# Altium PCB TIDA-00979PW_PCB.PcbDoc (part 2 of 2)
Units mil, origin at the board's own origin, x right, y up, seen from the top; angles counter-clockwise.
Board outline 2100 x 2800 mil, 4 copper layers (Top Layer, L02 - GND, L03 - SUPPLY, Bottom Layer), stack 61.17 mil thick; 75 components, 60 nets, 300 pads, 112 vias.
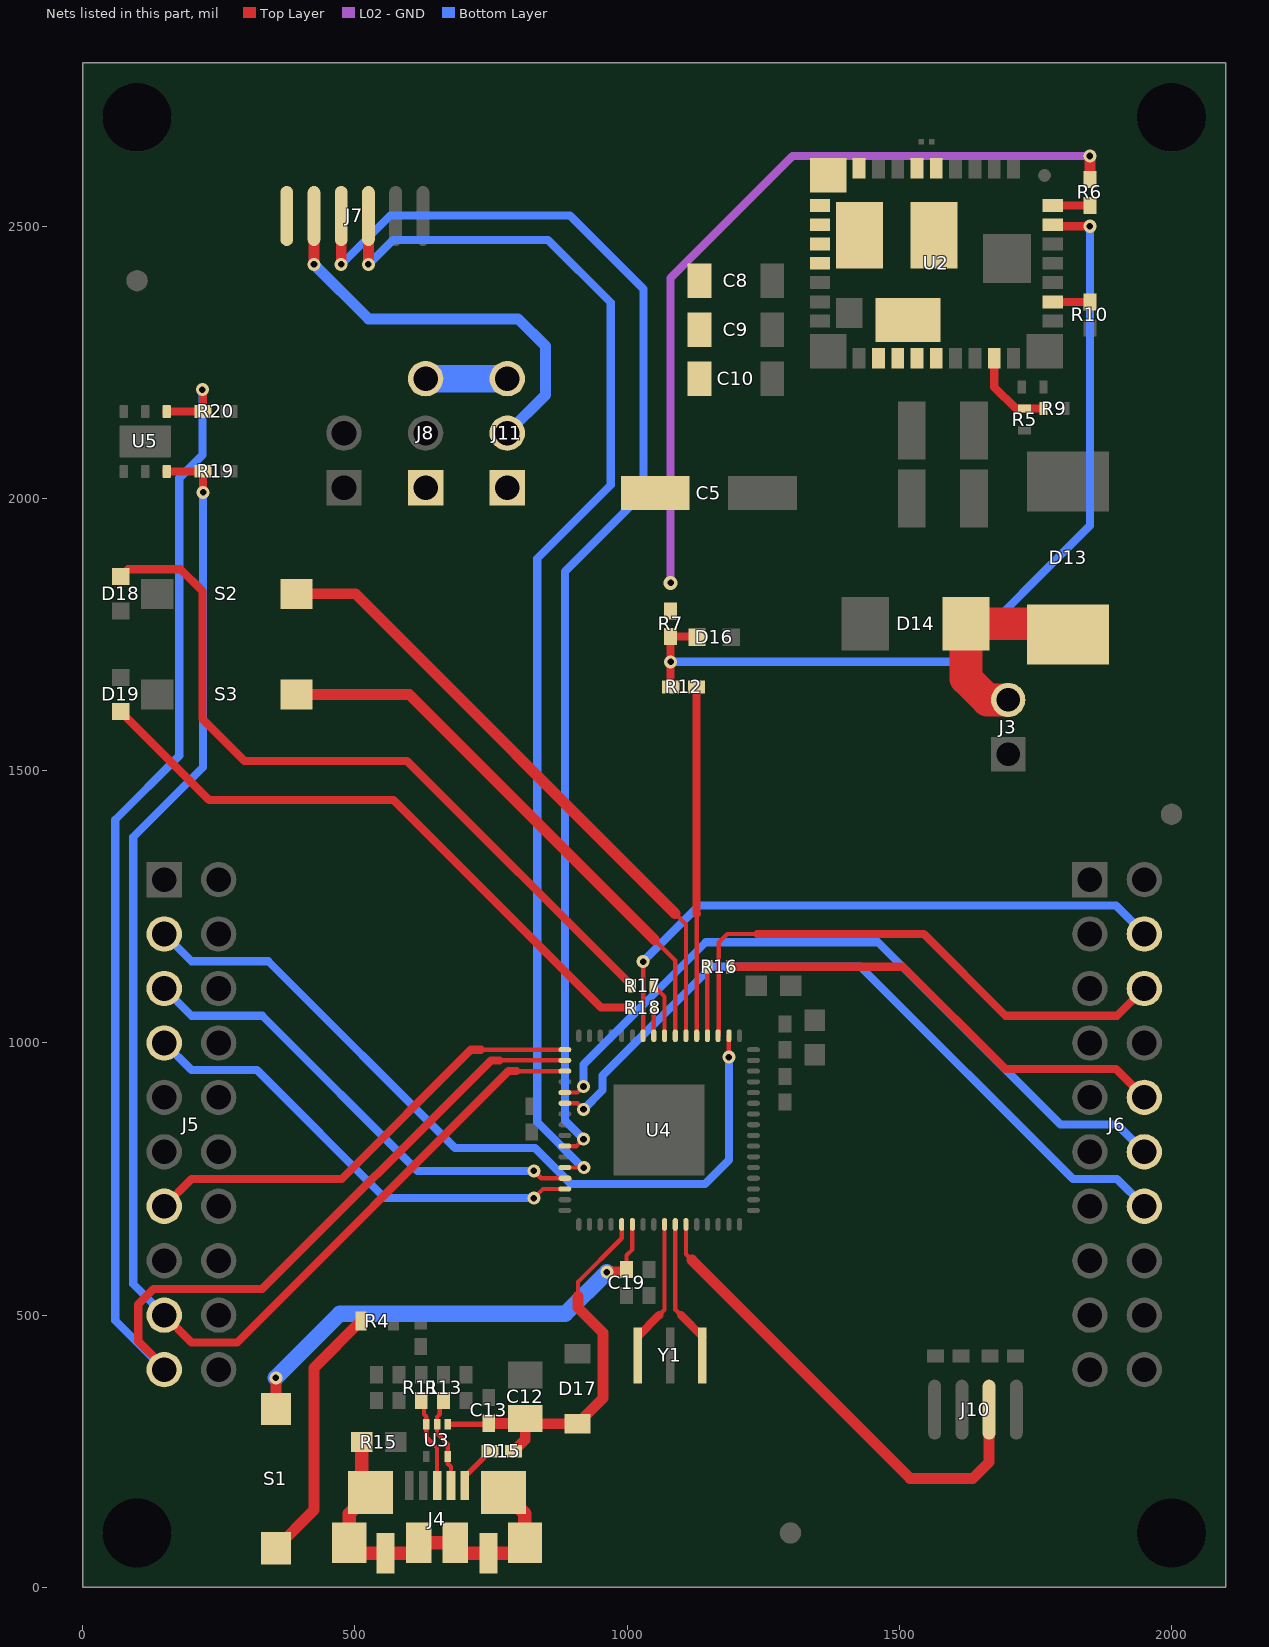
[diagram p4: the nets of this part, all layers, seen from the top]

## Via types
v1: diameter 24, hole 12, Top Layer to Bottom Layer, tented both sides, 72 vias
v2: diameter 19.68, hole 7.87, Top Layer to Bottom Layer, 19 vias
v3: diameter 26, hole 12, Top Layer to Bottom Layer, tented both sides, 15 vias
v4: diameter 19.68, hole 11.81, Top Layer to Bottom Layer, tented both sides, 6 vias

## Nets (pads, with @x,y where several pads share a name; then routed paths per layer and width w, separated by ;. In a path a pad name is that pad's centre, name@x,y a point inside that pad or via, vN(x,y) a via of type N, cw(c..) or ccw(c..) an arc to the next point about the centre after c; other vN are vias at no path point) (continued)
NetD13_2: D13.2 D14.2 J3.2 | length 395.4
  Top Layer w50: D13.2@1776.99,1769.51 D13.2@1810,1769.51
  Top Layer w60: J3.2@1700,1630 1662,1630 1622.52,1669.48 D14.2@1622.52,1770 D13.2@1790.51,1770
NetD15_2: D15.2 J4.1 | length 90
  Top Layer w10: J4.1@702.18,187.51 702.18,203.83 D15.2@748.35,250 D15.2@740,250
NetD16_2: D16.2 R7.1 R12.1 U2.35 | length 1634.8
  Top Layer w6: R12.1@1080,1654.38 R12.1@1080.38,1654 ; D16.2@1127.13,1746.38 D16.2@1128.5,1745 ; v1@1847.13,2502.87 v1(1850,2500)
  Top Layer w15: R12.1@1080,1654.38 v1(1080,1700) R7.1@1080,1746.38 D16.2@1127.13,1746.38 ; U2.35@1784.45,2500 v1(1850,2500)
  Bottom Layer w15: v1(1080,1700) 1600,1700 1850,1950 v1(1850,2500)
NetD18_2: D18.2 R17.2 | length 1399.1
  Top Layer w15: D18.2@70,1856.5 83.5,1870 180,1870 220,1830 220,1595 297,1518 596,1518 R17.2@1009,1105
NetD19_2: D19.2 R18.2 | length 1164.1
  Top Layer w15: D19.2@70,1608.5 232.5,1446 571,1446 952,1065 R18.2@1009,1065
NetJ4_2: J4.2 R13.1 U3.2 U3.5 | length 161.5
  Top Layer w8: R13.1@656,336.38 656,318 651,313 U3.2@651,299.53 651,283 670.69,263.31 U3.5@670.69,240.47 670.69,227.31 676.59,221.41 J4.2@676.59,187.51
NetJ4_3: J4.3 R11.1 U3.3 | length 169.3
  Top Layer w8: R11.1@621,338.38 R11.1@627,332.38 ; R11.1@627,338.38 R11.1@627,332.38 ; J4.3@651,187.51 651,256 631.32,275.68 U3.3@631.32,299.53 631.32,313.68 627,318 R11.1@627,332.38
NetJ4_6: J4.6 J4.7 J4.8 J4.9 J4.10 J4.11 J4.12 J4.13 R15.2 | length 717.7
  Top Layer w25: R15.2@512.5,267 512.5,190.97 J4.6@528.95,174.52 489.58,135.15 J4.8@489.58,82 489.58,62.51 J4.9@556.51,62.51 617.54,62.51 J4.10@617.54,82 J4.11@684.46,82 684.46,62.51 J4.12@745.49,62.51 812.42,62.51 J4.13@812.42,82 812.42,135.15 J4.7@773.05,174.52
NetJ6_10: J6.10 R16.1 | length 860.4
  Top Layer w15: R16.1@1189,1140 1507,1140 1694.85,952.15 1897.85,952.15 J6.10@1950,900
NetJ10_3: J10.3 U4.59 | length 891.2
  Top Layer w8: U4.59@1108.22,666.77 1108.22,611.78 1119,601
  Top Layer w20: 1119,601 1520,200 1635,200 1665,230 J10.3@1665,326.42
NetR4_1: R4.1 S1.1 | length 481.6
  Top Layer w20: S1.1@355,72.05 425,142.05 425,403 R4.1@511,489
NetR5_1: R5.1 R9.2 U2.27 | length 160.2
  Top Layer w15: U2.27@1674.3,2257.79 1674.3,2204.7 1714,2165 R5.1@1730,2165 R9.2@1765,2165
NetR6_1: R6.1 U2.36 | length 68.4
  Top Layer w15: U2.36@1781.58,2538.3 1849.92,2538.3 R6.1@1850,2538.38
NetR10_2: R10.2 U2.31 | length 68.6
  Top Layer w15: U2.31@1781.58,2361.13 1849.49,2361.13 R10.2@1850,2360.62
NetR17_1: R17.1 U4.24 | length 100
  Top Layer w8: R17.1@1049,1105 1068.85,1085.16 U4.24@1068.85,1013.23
NetR18_1: R18.1 U4.25 | length 51.8
  Top Layer w8: R18.1@1049,1065 1049.15,1064.84 U4.25@1049.15,1013.23
NetS2_2: S2.2 U4.22 | length 1171.3
  Top Layer w8: 1088,1238 1108.22,1217.78 U4.22@1108.22,1013.23
  Top Layer w20: S2.2@392.95,1824.99 501.01,1824.99 1088,1238
NetS3_2: S3.2 U4.23 | length 1036.2
  Top Layer w8: 1050,1190 1088.54,1151.47 U4.23@1088.54,1013.23
  Top Layer w20: S3.2@392.95,1639.99 600.01,1639.99 1050,1190
NetU2_6: U2.6 U2.7 U2.21 U2.22 U2.23 U2.24 U2.38 U2.41
NetU4_57: U4.57 Y1.3 | length 226.1
  Top Layer w8: 1059,500 1068.85,509.85 U4.57@1068.85,666.77
  Top Layer w15: Y1.3@1019.94,460.94 1059,500
NetU4_58: U4.58 Y1.1 | length 226.3
  Top Layer w8: U4.58@1088.54,666.77 1088.54,510.46 1099,500
  Top Layer w15: 1099,500 Y1.1@1138.06,460.94
P1.0_ACK: J5.3 U4.18 | length 1473.8
  Top Layer w8: v1@1186.98,980.01 U4.18@1186.98,1013.23
  Bottom Layer w15: J5.3@150,1200 200,1150 341,1150 684,807 831,807 897.04,740.96 1143.26,740.96 1187,784.7 v1@1187,980
  other v1: 1187,974
P1.1_NCS1: J6.6 U4.19 | length 1042.5
  Top Layer w8: U4.19@1167.3,1013.23 1168.37,1014.31 1168.37,1184.37 1184,1200 1239,1200
  Top Layer w15: 1239,1200 1545,1200 1695,1050 1900,1050 J6.6@1950,1100
P1.2_LPRST: R16.2 U4.20 | length 127.3
  Top Layer w8: U4.20@1147.61,1013.23 1147.61,1138.61 R16.2@1149,1140
P1.3_PWRGD: R12.2 U4.21 | length 641.3
  Top Layer w6: R12.2@1127.62,1654 R12.2@1127.91,1653.71
  Top Layer w8: U4.21@1127.91,1013.23 1127.91,1237.09
  Top Layer w15: R12.2@1127.62,1654 1127.62,1237.38 1127.91,1237.09
P2.0: J6.4 U4.26 | length 1120.9
  Top Layer w8: U4.26@1029.46,1013.23 v1(1029.46,1149.53)
  Bottom Layer w15: v1(1029.46,1149.53) 1132.08,1252.15 1897.85,1252.15 J6.4@1950,1200
P2.7_UCA0_CLK: J5.13 U4.33 | length 854.9
  Top Layer w8: 731.64,987.64 U4.33@885.77,987.64
  Top Layer w15: J5.13@150,700 200,750 476,750 713.64,987.64 731.64,987.64
P3.0_UCB0_SDA: J5.19 R20.1 U4.34 U5.1 | length 3120.1
  Top Layer w8: 765.95,967.95 U4.34@885.77,967.95
  Top Layer w15: J5.19@150,400 150,405 102.15,452.85 102.15,519.82 130.18,547.85 329.85,547.85 749.95,967.95 765.95,967.95 ; U5.1@154.37,2159.8 221.18,2159.8 R20.1@221.38,2160 221.38,2198.62 v1(220,2200)
  Bottom Layer w15: J5.19@150,400 60,490 60,1410 177.62,1527.62 177.62,2037.62 220,2080 v1(220,2200)
P3.1_UCB0_SCL: J5.17 R19.1 U4.35 U5.6 | length 2656.8
  Top Layer w8: 796.69,948.27 U4.35@885.77,948.27
  Top Layer w15: J5.17@150,500 200,450 284,450 782.27,948.27 796.69,948.27 ; U5.6@154.37,2049.57 220.94,2049.57 R19.1@221.38,2050 v1(221.38,2011.38)
  Bottom Layer w15: J5.17@150,500 93,557 93,1378 221.38,1506.38 v1(221.38,2011.38)
P3.3_UCA0_SIMO: J6.12 U4.37 | length 1361.8
  Top Layer w8: U4.37@885.77,908.9 908.9,908.9 v1(920,920)
  Bottom Layer w15: v1(920,920) 920,960.53 1144.46,1185 1461,1185 1796,850 1900,850 J6.12@1950,800
P3.4_UCA0_SOMI: J6.14 U4.38 | length 1375.3
  Top Layer w8: U4.38@885.77,889.21 908.9,889.21 v1(920,878.11)
  Bottom Layer w15: v1(920,878.11) 955,913.11 955,940 1155,1140 1429,1140 1819,750 1900,750 J6.14@1950,700
P4.1_UCB1_SIMO: J7.3 U4.42 | length 2412
  Top Layer w8: U4.42@885.77,810.47 906.97,810.47 v1(920,823.5)
  Top Layer w20: v1(475,2430) J7.3@475,2518.9
  Bottom Layer w15: v1(475,2430) 565,2520 895,2520 1030,2385 1030,2010 886,1866 886,857.5 v1(920,823.5)
P4.3_UCB1_CLK: J7.4 U4.44 | length 2312.3
  Top Layer w8: U4.44@885.77,771.1 v1@918.53,771.1
  Top Layer w20: v1(525,2430) J7.4@525,2518.9
  Bottom Layer w15: v1(525,2430) 570,2475 855,2475 970,2360 970,2025 835,1890 835,854.63 v1@918.53,771.1
  other v1: 920.53,771.1
P4.4_UCA1_TXD: J5.5 U4.45 | length 880.2
  Top Layer w8: v1(829,765) 842.58,751.42 U4.45@885.77,751.42
  Bottom Layer w15: J5.5@150,1100 200,1050 330,1050 615,765 v1(829,765)
P4.5_UCA1_RXD: J5.7 U4.46 | length 860.8
  Top Layer w8: v1(829,715) 845.73,731.73 U4.46@885.77,731.73
  Bottom Layer w15: J5.7@150,1000 200,950 320,950 555,715 v1(829,715)
VBUS: C12.1 C13.1 D15.1 D17.1 U3.1 U4.53 | length 753.4
  Top Layer w8: 910,534 910,561.18 990.09,641.26 U4.53@990.09,666.77
  Top Layer w10: U3.1@670.69,299.53 744.15,299.53 C13.1@746,301.38
  Top Layer w20: C13.1@746,301.38 804.38,301.38 C12.1@813,310 ; D15.1@791.65,250 813,271.35 C12.1@813,310 ; 910,534 910,513.63 956,467.63 956,347.53 D17.1@909,300.53 822.47,300.53 C12.1@813,310
VLED: C5.1 C8.1 C9.1 C10.1 J7.1 J11.1 R6.2 R7.2 U2.10 U2.11 U2.12 U2.13 U2.14 U2.15 U2.39 | length 1480.3
  Top Layer w20: R6.2@1850,2585.62 v1(1850,2629)
  Top Layer w24: C5.1@1041.89,2020 C5.1@1051.89,2010
  L02 - GND w15: v3(1080,1845) 1080,2405 1304,2629 v1(1850,2629)
VREG: J7.2 J11.2 | length 765
  Top Layer w20: v1(425,2430) J7.2@425,2518.9
  Bottom Layer w20: v1(425,2430) 525,2330 800,2330 850,2280 850,2190 J11.2@780,2120
VTLC: J8.3 J11.3 | length 150
  Bottom Layer w50: J8.3@630,2220 J11.3@780,2220
VUSB: C19.1 J8.1 S1.2 U4.54 | length 870.9
  Top Layer w8: C19.1@999,583.62 999,609.88 1009.78,620.65 U4.54@1009.78,666.77
  Top Layer w20: S1.2@355,327.95 v1(355,385) ; v1(963,579) 994.38,579 C19.1@999,583.62
  Bottom Layer w30: v1(355,385) 472.5,502.5 886.5,502.5 v1(963,579)
pads on no net: FID4.1 FID5.1 FID6.1 J4.4 J5.6 J5.8 J5.10 J5.12 J5.14 J5.16 J5.18 J5.20 J6.1 J6.3 J6.5 J6.7 J6.9 J6.11 J6.13 J6.15 J6.17 J6.19 SH-J8.0 SH-J9.0 SH-J11.0 U2.2 U2.3 U2.25 U4.8 U4.9 U4.10 U4.12 U4.13 U4.27 U4.28 U4.29 U4.30 U4.31 U4.32 U4.36 U4.41 U4.43 U4.47 U4.48 U4.60 U4.61 U4.62 U4.63 U5.3 U5.4 U5.7
copper on no net:
  other v2: 77.6,2085 115,2085 152.4,2085 77.6,2124.37 115,2124.37 152.4,2124.37

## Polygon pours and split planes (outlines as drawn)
VLED on Top Layer "VLED_L01_P008" (solid, remove dead copper, pour order 8): 1160,2395 1160,2405 1195,2440 1275,2440 1295,2440 1310,2425 1325,2410 1450,2410 1480,2410 1470,2420 1470,2547 1440,2577 1440,2790 350,2790 350,2030 605,1775 1110,1775 1160,1825
GND on Top Layer "GND_L01_P006" (solid, remove dead copper, pour order 6): 1565,2190 1565,2215 1555,2225 1445,2225 1440,2230 1440,2375 1450,2385 1475,2385 1505,2385 1510,2390 1510,2635 1515,2640 1540,2640 1543,2643 1543,2795 1510,2795 1450,2795 1450,2585 1480,2555 1480,2410 1325,2410 1295,2440 1275,2440 1230,2440 1210,2440 1200,2430 1175,2405 1175,1975 1175,1710 1185,1700 1545,1700 1565,1720
NetC6_1 on Top Layer "NETC6_1_L01_P004" (solid, remove dead copper, pour order 4): 1655,2280 1625,2280 1625,2225 1600,2200 1600,2180 1600,1935 1615,1920 1725,1920 2100,1920 2100,2130 1775,2130 1765,2140 1711.72,2140 1665,2186.72 1655,2196.72
NetU2_6 on Top Layer "NETU2_6_L01_P002" (solid, remove dead copper, pour order 2): 1585,2235 1450,2235 1450,2370 1455,2375 1510,2375 1520,2385 1520,2630 1580,2630 1580,2575 1625,2530 1625,2516.49 1625,2290 1620,2285 1590,2285 1585,2280
AGND on Top Layer "AGND_L01_P000" (solid, remove dead copper, pour order 0): 1590,2585 1625,2550 1625,2290 1630,2285 1730,2285 1730,2235 1740,2225 1740,2195 1745,2190 1785,2190 1785,2145 1790,2140 2105,2140 2105,2335 2105,2805 1590,2805 1557,2805 1557,2643 1560,2640 1585,2640 1590,2635
GND on L02 - GND "GND_L02_P010" (solid, remove dead copper, pour order 10): 0,2800 2100,2800 2100,0 0,0
VUSB on L03 - SUPPLY "VUSB_L03_P014" (solid, remove dead copper, pour order 14): 1020,-10 1020,555 978.5,596.5 725,850 725,891.97 725,2050 715,2060 600,2060 520,1980 450,1910 0,1910 0,-15
+3V3 on L03 - SUPPLY "+3V3_L03_P012" (solid, remove dead copper, pour order 12): 0,1925 305,1925 445,2065 710,2065 725,2050 725,860 725,850 1000,575 1025,550 1025,0 2100,0 2100,2800 0,2800
GND on Bottom Layer "GND_L04_P018" (solid, remove dead copper, pour order 18): 2105,2805 -5,2805 -5,-5 2105,-5
AGND on Bottom Layer "AGND_L04_P016" (solid, remove dead copper, pour order 16): 2110,2350 1650,2350 1635,2365 1635,2410 1635,2815 2085,2815 2110,2815 2110,2365

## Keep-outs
Keep-Out Layer:
  lines w10: -5,0 ccw(c0,0) 0,-5 ; -5,0 ccw(c0,0) 0,-5 ; -5,0 -5,2800 ; -5,2800 cw(c0,2800) 0,2805 ; -5,2800 cw(c0,2800) 0,2805 ; 0,-5 2100,-5 ; 0,2805 2100,2805 ; 2100,-5 ccw(c2100,0) 2105,0 ; 2100,-5 ccw(c2100,0) 2105,0 ; 2100,2805 cw(c2100,2800) 2105,2800 ; 2100,2805 cw(c2100,2800) 2105,2800 ; 2105,0 2105,2800
  text ".Layer_Name" at 577,-858.49 h60

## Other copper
Top Layer:
  text ".Layer_Name" at 577,-858.49 h60
L02 - GND:
  pour cut-out: 1645,1690 1760,1690 1760,1475 1645,1475
  text "L02 - GND" at 577,-858.49 h60
L03 - SUPPLY:
  text "L03 - SUPPLY" at 577,-858.49 h60
Bottom Layer:
  pour cut-out: 1650,1680 1750,1680 1750,1480 1650,1480
  text ".Layer_Name" at 577,-858.49 h60

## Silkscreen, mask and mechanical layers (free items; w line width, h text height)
Top Overlay:
  region: 1355,1595 1355,1295 1455,1295 1455,1595
  text "'.PRJ_Number'.PCB_Rev" at 1650,575 h108.27 r90
  text "ISFA-EVM-979PW" at 1745,575 h108.27 r90
  text ".Layer_Name" at 577,-858.49 h60
Bottom Overlay:
  text ".Layer_Name" at 577,-858.49 h60
Top Paste:
  text ".Layer_Name" at 577,-858.49 h60
Bottom Paste:
  text ".Layer_Name" at 577,-858.49 h60
Top Solder:
  text ".Layer_Name" at 577,-858.49 h60
  text ".Layer_Name" at 577,-858.49 h60
Bottom Solder:
  text ".Layer_Name" at 577,-858.49 h60
Drill Guide:
  text ".Layer_Name" at 577,-858.49 h60
M1 Board Outline:
  the board outline again, w10
  text ".Layer_Name" at 577,-858.49 h60
M2 Board Dimensions:
  rectangle: 125,-400 500,-275
  rectangle: 0,-275 125,-150
  lines w7: 0,-275 1000,-275 ; 125,-400 125,-150 ; 250,-400 250,-150 ; 500,-400 500,-150 ; 750,-400 750,-150 ; 0,-400 0,-150 1000,-150 1000,-400 0,-400
  text ".Layer_Name" at 577,-858.49 h60
M3 3D STEP Top:
  text ".Layer_Name" at 577,-858.49 h60
M4 3D STEP Bottom:
  text ".Layer_Name" at 577,-858.49 h60
M5 Assembly Top:
  lines w10: -292,-930.17 6308,-930.17 ; -292,-726.83 6310,-726.83 ; -292,-523.5 -292,-1133.5 3713,-1133.5 6310,-1133.5 6310,-523.5 -291.5,-523.5 -291.5,-1133.5 1284,-1133.5 ; 2173,-1133.5 2173,-523.5 ; 3440,-726.83 3440,-523.5 ; 4280,-726.83 4280,-523.5 ; 4902,-1140 4902,-937.17
  text "COMPONENTS MARKED 'DNP' SHOULD NOT BE POPULATED." at 1153.5,-318.5 h60
  text "ASSEMBLY VARIANT:" at 1153,-434 h60
  text ".VariantName" at 2189,-434 h60
  text "PCB VIEWED FROM TOP SIDE" at -228.5,-655.67 h60
  text "BOARD #:" at 2248,-655.67 h60
  text ".PRJ_Number" at 2793.5,-655.67 h60
  text "REV:" at 3638,-655.67 h60
  text ".PCB_Rev" at 3929.5,-655.67 h60
  text "SVN REV:" at 4476,-655.67 h60
  text ".VersionControl_RevNumber" at 4982,-655.67 h60
  text "TID #:" at 2248,-859 h60
  text ".TID" at 2793.5,-859 h60
  text "PLOT NAME =" at -228.5,-1064.34 h60
  text ".plot_File_Name" at 577,-1064.34 h60
  text "GENERATED    :" at 2250,-1064.34 h60
  text ".Print_Date" at 3119.5,-1064.34 h60
  text ".Print_Time" at 3848.5,-1064.34 h60
  text "TEXAS INSTRUMENTS" at 5113,-1064.34 h60
M6 Assembly Bottom:
  lines w10: -292.5,-727.33 6309.5,-727.33 ; -290.5,-930.67 6309.5,-930.67 ; 1115.5,-1140.5 1115.5,-937.67 ; 1737.5,-727.33 1737.5,-524 ; 2577.5,-727.33 2577.5,-524 ; 3844.5,-1134 3844.5,-524 ; 4733.5,-1134 6309,-1134 6309,-524 -292.5,-524 -292.5,-1134 2304.5,-1134 6309.5,-1134 6309.5,-524
  text "COMPONENTS MARKED 'DNP' SHOULD NOT BE POPULATED." at 6102,-318 h60
  text ".VariantName" at 5058,-434 h60
  text "ASSEMBLY VARIANT:" at 6097,-434 h60
  text ".VersionControl_RevNumber" at 1035.5,-656.17 h60
  text "SVN REV:" at 1541.5,-656.17 h60
  text ".PCB_Rev" at 2088,-656.17 h60
  text "REV:" at 2379.5,-656.17 h60
  text ".PRJ_Number" at 3224,-656.17 h60
  text "BOARD #:" at 3769.5,-656.17 h60
  text "PCB VIEWED FROM BOTTOM SIDE" at 6246,-656.17 h60
  text ".TID" at 3224,-859.5 h60
  text "TID #:" at 3769.5,-859.5 h60
  text "TEXAS INSTRUMENTS" at 904.5,-1064.84 h60
  text ".Print_Time" at 2169,-1064.84 h60
  text ".Print_Date" at 2898,-1064.84 h60
  text "GENERATED    :" at 3767.5,-1064.84 h60
  text ".plot_File_Name" at 5440.5,-1064.84 h60
  text "PLOT NAME =" at 6246,-1064.84 h60
M9 Title Sheet:
  drawing of 57 lines, arcs and shapes, not listed
  text "1" at 739.84,8036.5 h70
  text "2" at 3235.5,8036.5 h70
  text "3" at 5724.84,8036.5 h70
  text "4" at 8231.51,8036.5 h70
  text "5" at 10730.5,8036.5 h70
  text "6" at 13235.5,8036.5 h70
  text "A" at -416.5,6893.5 h70
  text "A" at 14383.5,6893.5 h70
  text "B" at -416.5,4513.5 h70
  text "B" at 14383.5,4513.5 h70
  text "C" at -416.5,2138.5 h70
  text "C" at 14383.5,2138.5 h70
  text "PROJECT TITLE:" at 11343.5,277.5 h45
  text ".PRJ_Title" at 11393.5,144.17 h70
  text "DESIGNED FOR:" at 11343.5,-23.5 h45
  text ".PRJ_Customer" at 11393.5,-163.5 h70
  text "D" at -416.5,-231.5 h70
  text "D" at 14383.5,-231.5 h70
  text "FILE NAME:" at 11343.5,-323.5 h45
  text ".PCB_File_Name_No_Path" at 11393.5,-443.5 h70
  text "Texas Instruments (TI) and/or its licensors do not warrant the accuracy or completeness of this specification" at 6374,-605.34 h45
  text "ENGINEER:" at 11343.5,-613.5 h45
  text "LAYOUT BY:" at 12848.5,-613.5 h45
  text "or any information contained therein. TI and/or its licensors do not warrant that this design will meet" at 6329.01,-718 h45
  text ".PRJ_Engineer" at 11393.5,-768.49 h70
  text ".PCB_Layout" at 12899,-768.49 h70
  text "the specifications, will be suitable for your application or fit for any particular purpose, or will operate in" at 6329.01,-830.67 h45
  text ".Layer_Name" at 577,-858.49 h60
  text "ALTIUM DESIGNER VERSION:" at 12848.5,-923.5 h45
  text "an implementation. TI and/or its licensors do not warrant that the design is production worthy. You should" at 6329.01,-943.33 h45
  text "completely validate and test your design implementation to confirm the system functionality for your application." at 6374,-1056 h45
  text ".print_Scale" at 11393.5,-1056.83 h70
  text ".Application_BuildNumber" at 12899,-1056.83 h70
  text "1" at 739.84,-1263.5 h70
  text "2" at 3235.5,-1263.5 h70
  text "3" at 5724.84,-1263.5 h70
  text "4" at 8231.51,-1263.5 h70
  text "5" at 10730.5,-1263.5 h70
  text "6" at 13235.5,-1263.5 h70
M10 Fab Notes:
  drawing of 173 lines, arcs and shapes, not listed
  text "DESIGN INFORMATION" at 12378.02,6201 h60
  text "MIN. TRACK WIDTH:" at 11733.46,6021 h60
  text "8" at 12829.7,6021 h60
  text "MIL" at 12984.46,6021 h60
  text "MIN. CLEARANCE:" at 11733.46,5889 h60
  text "0.2" at 12769.7,5889 h60
  text "mm" at 12984.46,5889 h60
  text "MIN. VIA PAD SIZE:" at 11733.46,5757 h60
  text "24" at 12799.71,5757 h60
  text "MIL" at 12984.46,5757 h60
  text "0.05mm (2MIL)" at 12428.46,5615.29 h60
  text "MINIMUM ANNULAR RING" at 11404.23,5611 h60
  text "EXTERNAL" at 13136.46,5611 h60
  text "PER" at 11604.23,5493 h60
  text "IPC-D-275 CLASS 2 LEVEL C" at 11824.23,5493 h60
  text "MIL, HOLES" at 13312.46,5380.71 h60
  text "+/-" at 12920,5380 h60
  text "+/-" at 13774,5380 h60
  text "REGISTRATION TOLERANCES:" at 11404.23,5375 h60
  text "METAL" at 12604,5375 h60
  text "5" at 13180.2,5375 h60
  text "3" at 14013.2,5375 h60
  text "MIL" at 14129.46,5375 h60
  text "+/-" at 13774,5262 h60
  text "HOLE SIZE TOLERANCE (UNLESS OTHERWISE SPECIFIED):" at 11404.23,5257 h60
  text "3" at 14013.2,5257 h60
  text "MIL" at 14129.46,5257 h60
  text "MATERIAL:" at 11329.46,5047.54 h60
  text "FR-4 High Tg" at 12315.9,4907.21 h60
  text "FR-408" at 11750.46,4898.64 h60
  text "OTHER" at 13238.46,4898.64 h60
  text "X" at 12161,4895 h60
  text "62 MIL (1.6mm) +/-10%" at 12070.56,4735.92 h60
  text "THICKNESS:" at 11404.23,4731.64 h60
  text "X" at 11942.4,4731.64 h60
  text "OTHER" at 13355.46,4731.64 h60
  text "TOLERANCE:" at 11404.23,4573.64 h60
  text "X" at 12243.53,4573.64 h60
  text "ANSI IPC-6012 TYPE 3 CLASS 2" at 12430.48,4573.64 h60
  text "OTHER +/-" at 12430.46,4417.64 h60
  text "BOW & TWIST:" at 11404.23,4260.64 h60
  text "X" at 12243.53,4260.64 h60
  text "ANSI IPC-6012 TYPE 3 CLASS 2" at 12430.48,4260.64 h60
  text "OTHER +/-" at 12430.46,4102.13 h60
  text "DRILLING:" at 11329.46,3963.64 h60
  text "REFERENCE:" at 11404.23,3846.64 h60
  text "X" at 12052.46,3846.64 h60
  text "AS SHOWN" at 12239.46,3846.64 h60
  text "X" at 12953.46,3846.64 h60
  text "NC_DRILL FILES" at 13090.46,3846.64 h60
  text "PTH MIN COPPER THICKNESS:" at 11404.23,3688.64 h60
  text "X" at 12754.46,3688.64 h60
  text "1MIL" at 12891.46,3688.64 h60
  text "OTHER" at 13388.46,3688.64 h60
  text "BOARD FINISH:" at 11329.46,3529.64 h60
  text "SILKSCREEN:" at 11484.68,3411.64 h60
  text "X" at 12433.46,3411.64 h60
  text "TOP" at 12559.46,3411.64 h60
  text "X" at 12943.46,3411.64 h60
  text "BOTTOM" at 13070.46,3411.64 h60
  text "SILKSCREEN COLOR:" at 11484.68,3244.64 h60
  text "X" at 12432.42,3244.64 h60
  text "WHITE" at 12559.46,3244.64 h60
  text "OTHER" at 13070.46,3244.64 h60
  text "X" at 12563.42,3085.44 h60
  text "GREEN" at 12690.46,3085.44 h60
  text "OTHER" at 13308.46,3085.44 h60
  text "SOLDER RESIST COLOR:" at 11484.68,3074.64 h60
  text "X" at 12563.42,2915.44 h60
  text "MATTE" at 12690.46,2915.44 h60
  text "SEMI-GLOSS" at 13308,2914.8 h60
  text "IMMERSION GOLD (ENIG)" at 12390.46,2726.92 h60
  text "ENEPIG" at 13728,2723.64 h60
  text "SURFACE FINISH:" at 11329.46,2722.64 h60
  text "X" at 12203.51,2722.64 h60
  text "IMM. TIN/SILVER OR EQUIV" at 11659,2565.64 h60
  text "OTHER" at 13090.46,2565.64 h60
  text "ARRAY/PANEL:" at 11329.46,2386.64 h60
  text "CUT AND TRIM PER M1 BOARD OUTLINE" at 12390.46,2382.35 h60
  text "N.C. ROUTE" at 12390.46,2230.64 h60
  text "X" at 13069.46,2230.64 h60
  text "V. SCORE" at 13256.46,2230.64 h60
  text "CERTIFICATION:" at 11329.46,2093.64 h60
  text "MATERIALS AND WORKMANSHIP FOR ALL PCBS" at 12054.46,2093.64 h60
  text "TO MEET OR EXCEED THE REQUIREMENTS OF:" at 12054.46,1995.64 h60
  text "X" at 11680.96,1859.13 h60
  text "ANSI IPC-A-600F CLASS ->" at 11819.96,1859.13 h60
  text "X" at 13459.02,1859.13 h60
  text "2" at 13577.96,1859.14 h60
  text "1" at 13262.96,1857.64 h60
  text "3" at 13931.96,1857.64 h60
  text "X" at 12495.02,1699.64 h60
  text "RoHS" at 12631.96,1699.64 h60
  text "OTHER" at 13276.36,1699.64 h60
  text "PER ORDER" at 13673.42,1699.64 h60
  text "ALL BOARDS MUST MEET OR EXCEED UL94-V0 REQUIREMENTS." at 11357,1534 h60
  text "PCB MUST BEAR THE UL94V-0 UL REGISTERED MATERIAL ID NUMBER" at 11357,1414 h60
  text "ADDITIONAL REQUIREMENTS:" at 11329.46,1240.64 h60
  text "MICROSECTION:" at 11404.23,1125.64 h60
  text "YES" at 12309.96,1125.64 h60
  text "REQUIRED" at 13171.46,969.49 h60
  text "BARE BOARD ELEC. TEST:" at 11404.23,966.64 h60
  text "NONE" at 12709.96,966.64 h60
  text "X" at 13044.46,966.64 h60
  text "PER ORDER" at 13763.46,966.64 h60
  text ".Layer_Name" at 577,-858.49 h60
M11 Gerber Information:
  lines w10: -292,-930.17 6308,-930.17 ; -292,-726.83 6310,-726.83 ; -292,-523.5 -292,-1133.5 3713,-1133.5 6310,-1133.5 6310,-523.5 -291.5,-523.5 -291.5,-1133.5 1284,-1133.5 ; 2173,-1133.5 2173,-523.5 ; 3440,-726.83 3440,-523.5 ; 4280,-726.83 4280,-523.5 ; 4902,-1140 4902,-937.17
  text "ALL ARTWORK VIEWED FROM TOP SIDE" at -228.5,-655.67 h60
  text "BOARD #:" at 2248,-655.67 h60
  text ".PRJ_Number" at 2793.5,-655.67 h60
  text "REV:" at 3638,-655.67 h60
  text ".PCB_Rev" at 3929.5,-655.67 h60
  text "SVN REV:" at 4476,-655.67 h60
  text ".VersionControl_RevNumber" at 4982,-655.67 h60
  text "LAYER NAME =" at -228.5,-858.49 h60
  text "TID #:" at 2248,-859 h60
  text ".TID" at 2793.5,-859 h60
  text "PLOT NAME =" at -228.5,-1064.34 h60
  text ".plot_File_Name" at 577,-1064.34 h60
  text "GENERATED    :" at 2250,-1064.34 h60
  text ".Print_Date" at 3119.5,-1064.34 h60
  text ".Print_Time" at 3848.5,-1064.34 h60
  text "TEXAS INSTRUMENTS" at 5113,-1064.34 h60
M12 Stackup:
  drawing of 295 lines, arcs and shapes, not listed
  text "Layer" at 9780.58,7760 h60
  text "Name" at 10190.49,7760 h60
  text "Material" at 11120.23,7760 h60
  text "Thickness" at 11980,7760 h60
  text "Constant" at 12629.84,7760 h60
  text "Board Layer Stack" at 13199.7,7760 h60
  text "1" at 9780.58,7640 h60
  text "Top Overlay" at 10190.49,7640 h60
  text "2" at 9780.58,7520 h60
  text "Top Solder" at 10190.49,7520 h60
  text "Solder Resist" at 11120.23,7520 h60
  text "0,40mil" at 11980,7520 h60
  text "3,5" at 12629.84,7520 h60
  text "3" at 9780.58,7400 h60
  text "Top Layer" at 10190.49,7400 h60
  text "Copper" at 11120.23,7400 h60
  text "1,40mil" at 11980,7400 h60
  text "4" at 9780.58,7280 h60
  text "Dielectric1" at 10190.49,7280 h60
  text "FR-4" at 11120.23,7280 h60
  text "10,00mil" at 11980,7280 h60
  text "4,8" at 12629.84,7280 h60
  text "5" at 9780.58,7160 h60
  text "L02 - GND" at 10190.49,7160 h60
  text "Copper" at 11120.23,7160 h60
  text "1,40mil" at 11980,7160 h60
  text "6" at 9780.58,7040 h60
  text "Dielectric 3" at 10190.49,7040 h60
  text "FR-4" at 11120.23,7040 h60
  text "35,57mil" at 11980,7040 h60
  text "4,8" at 12629.84,7040 h60
  text "7" at 9780.58,6920 h60
  text "L03 - SUPPLY" at 10190.49,6920 h60
  text "Copper" at 11120.23,6920 h60
  text "1,40mil" at 11980,6920 h60
  text "8" at 9780.58,6800 h60
  text "Dielectric 2" at 10190.49,6800 h60
  text "FR-4" at 11120.23,6800 h60
  text "10,00mil" at 11980,6800 h60
  text "4,8" at 12629.84,6800 h60
  text "9" at 9780.58,6680 h60
  text "Bottom Layer" at 10190.49,6680 h60
  text "Copper" at 11120.23,6680 h60
  text "1,40mil" at 11980,6680 h60
  text "10" at 9780.58,6560 h60
  text "Bottom Solder" at 10190.49,6560 h60
  text "Solder Resist" at 11120.23,6560 h60
  text "0,40mil" at 11980,6560 h60
  text "3,5" at 12629.84,6560 h60
  text "11" at 9780.58,6440 h60
  text "Bottom Overlay" at 10190.49,6440 h60
  text ".Layer_Name" at 577,-858.49 h60
M13 Component Bodies Top:
  text ".Layer_Name" at 577,-858.49 h60
M14 Component Bodies Bottom:
  text ".Layer_Name" at 577,-858.49 h60
M15 Courtyards Top:
  text ".Layer_Name" at 577,-858.49 h60
M16 Courtyards Bottom:
  text ".Layer_Name" at 577,-858.49 h60
Drill Drawing:
  circle w10: c5363.82,3266.02 r16.6
  circle w10: c5363.82,3266.02 r27.67
  lines w10: 5336.16,2629.68 5349.99,2629.68 5349.99,2615.85 5377.66,2615.85 5377.66,2629.68 5391.49,2629.68 5391.49,2657.35 5377.66,2657.35 5377.66,2671.18 5349.99,2671.18 5349.99,2657.35 5336.16,2657.35 5336.16,2629.68 ; 5336.16,2740.35 5363.82,2754.18 5391.49,2740.35 5377.66,2768.02 5391.49,2795.68 5363.82,2781.85 5336.16,2795.68 5349.99,2768.02 5336.16,2740.35 ; 5336.16,2920.18 5391.49,2920.18 5363.82,2864.85 5336.16,2920.18 ; 5336.16,3003.18 5349.99,3003.18 5363.82,2989.35 5377.66,3003.18 5391.49,3003.18 5377.66,3017.02 5391.49,3030.85 5377.66,3030.85 5363.82,3044.68 5349.99,3030.85 5336.16,3030.85 5349.99,3017.02 5336.16,3003.18 ; 5336.16,3113.85 5391.49,3113.85 5391.49,3169.18 5336.16,3169.18 5336.16,3113.85
  lines w12: 5286,2578.5 8363.99,2578.5 ; 5286,3325.5 8363.99,3325.5 ; 5624.01,2454 5624.01,3450 ; 5956.17,2454 5956.17,3450 ; 6592.65,2454 6592.65,3450 ; 6851.85,2454 6851.85,3450 ; 7227.09,2454 7227.09,3450 ; 7951.64,2454 7951.64,3450 ; 5286,2454 8363.99,2454 8363.99,3450 5286,3450 5286,2454
  text "Symbol" at 5360.7,3362.85 h72
  text "Quantity" at 5661.36,3362.85 h72
  text "Finished Hole Size" at 5993.52,3362.85 h72
  text "Plated" at 6630,3362.85 h72
  text "Hole Type" at 6889.2,3362.85 h72
  text "Drill Layer Pair" at 7264.44,3362.85 h72
  text "Tolerance" at 7988.99,3362.85 h72
  text "4" at 5661.36,3238.35 h60
  text "125.98mil (3.200mm)" at 5993.52,3238.35 h60
  text "NPTH" at 6630,3238.35 h60
  text "Round" at 6889.2,3238.35 h60
  text "Top Layer - Bottom Layer" at 7264.44,3238.35 h60
  text "19" at 5661.36,3113.85 h60
  text "7.87mil (0.200mm)" at 5993.52,3113.85 h60
  text "PTH" at 6630,3113.85 h60
  text "Round" at 6889.2,3113.85 h60
  text "Top Layer - Bottom Layer" at 7264.44,3113.85 h60
  text "6" at 5661.36,2989.35 h60
  text "11.81mil (0.300mm)" at 5993.52,2989.35 h60
  text "PTH" at 6630,2989.35 h60
  text "Round" at 6889.2,2989.35 h60
  text "Top Layer - Bottom Layer" at 7264.44,2989.35 h60
  text "87" at 5661.36,2864.85 h60
  text "12.00mil (0.305mm)" at 5993.52,2864.85 h60
  text "PTH" at 6630,2864.85 h60
  text "Round" at 6889.2,2864.85 h60
  text "Top Layer - Bottom Layer" at 7264.44,2864.85 h60
  text "2" at 5661.36,2740.35 h60
  text "43.31mil (1.100mm)" at 5993.52,2740.35 h60
  text "PTH" at 6630,2740.35 h60
  text "Round" at 6889.2,2740.35 h60
  text "Top Layer - Bottom Layer" at 7264.44,2740.35 h60
  text "48" at 5661.36,2615.85 h60
  text "45.28mil (1.150mm)" at 5993.52,2615.85 h60
  text "PTH" at 6630,2615.85 h60
  text "Round" at 6889.2,2615.85 h60
  text "Top Layer - Bottom Layer" at 7264.44,2615.85 h60
  text "166 Total" at 5661.36,2491.35 h60
  text ".Layer_Name" at 577,-858.49 h60
M17 Embedded Cavity:
  text ".Layer_Name" at 577,-858.49 h60
M18 Embedded Assembly:
  text ".Layer_Name" at 577,-858.49 h60
M19 Embedded Keepout:
  text ".Layer_Name" at 577,-858.49 h60

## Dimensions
0,0 to 2100,0 on M2 Board Dimensions
0,0 to 0,2800 on M2 Board Dimensions
0,-400 to 1000,-400 on M2 Board Dimensions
